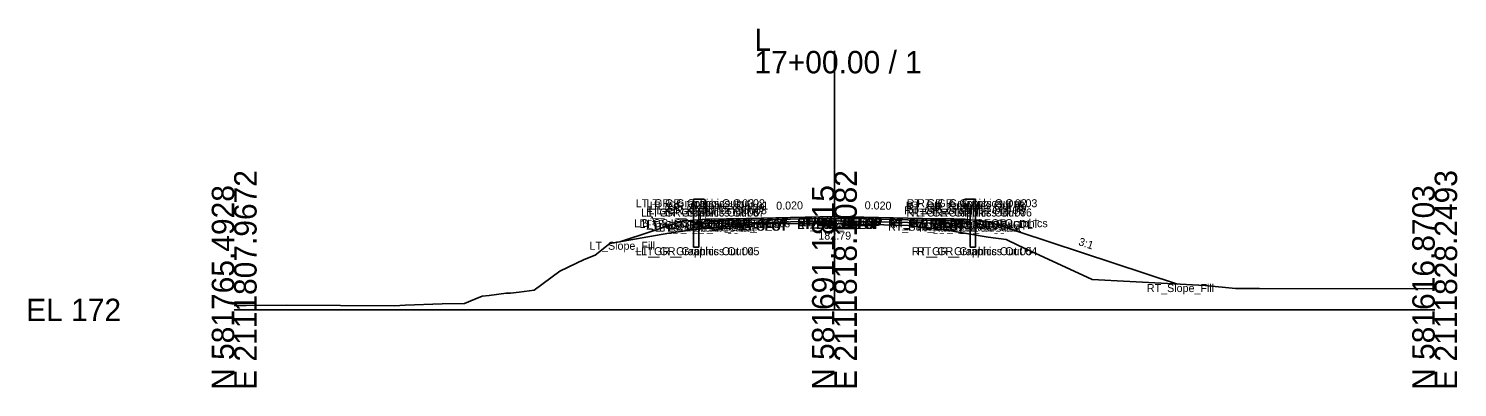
# Model space of a CAD drawing. Extents: x -26 to 3453, y -333 to 9539.
# Drawn here: x -25.7 to 152.8, y 7490.3 to 7535.2 of the extents above; entities that cross this region are included whole.
import ezdxf

# ---------------------------------------------------------------- set-up
doc = ezdxf.new("R2010")
doc.units = 0
for name, color, linetype in [('Default', 7, 'Continuous'), ('Exist Cross Section Cell', 7, 'Continuous'), ('Exist XS Center Line Elevation Label', 7, 'Continuous'), ('Exist XS Ground Line', 7, 'Continuous'), ('Prop CMT Guardrail Graphics', 7, 'Continuous'), ('Prop CMT Pvmt Course 1', 7, 'Continuous'), ('Prop CMT Pvmt Course 2', 7, 'Continuous'), ('Prop CMT Pvmt Course 3', 7, 'Continuous'), ('Prop CMT Pvmt Surface', 7, 'Continuous'), ('Prop CMT Pvmt Surface Shoulder', 7, 'Continuous'), ('Prop CMT Shld Paved Course 1', 7, 'Continuous'), ('Prop CMT Shld Paved Course 2', 7, 'Continuous'), ('Prop CMT Shld Paved Course 3', 7, 'Continuous'), ('Prop CMT Slope Grass', 7, 'Continuous'), ('Prop CMT Subgrade Earthwork', 7, 'Continuous'), ('Prop XS SE Text', 7, 'Continuous'), ('Prop XS Side Slope Text', 7, 'Continuous'), ('Scratch_Level_0', 7, 'Continuous')]:
    doc.layers.add(name, color=color, linetype=linetype)

msp = doc.modelspace()

# ---------------------------------------------------------------- linework, layer by layer
at = {"layer": 'Exist Cross Section Cell'}
for p, q in [((75, 7500), (75, 7532.38)), ((0, 7500), (75, 7500)), ((75, 7500), (150, 7500))]:
    msp.add_line(p, q, dxfattribs=at)
at = {"layer": 'Exist XS Ground Line'}
for p, q in [((46.92, 7508.3), (54.29, 7509.61)), ((54.29, 7509.61), (57.27, 7510.01)), ((57.27, 7510.01), (65.13, 7510.75)), ((65.13, 7510.75), (66.97, 7510.76)), ((66.97, 7510.76), (74.65, 7510.79)), ((74.65, 7510.79), (75, 7510.79)), ((75, 7510.79), (76.59, 7510.75)), ((76.59, 7510.75), (84.26, 7510.57)), ((84.26, 7510.57), (88.54, 7510.04)), ((88.54, 7510.04), (94.19, 7509.1)), ((94.19, 7509.1), (96.46, 7508.79)), ((45.09, 7506.86), (46.92, 7508.3)), ((96.46, 7508.79), (97.93, 7508.09)), ((97.93, 7508.09), (107.19, 7503.82)), ((40.68, 7504.84), (43.72, 7506.32)), ((43.72, 7506.32), (45.09, 7506.86)), ((37.47, 7502.46), (40.68, 7504.84)), ((107.19, 7503.82), (121.3, 7503.04)), ((31.86, 7501.81), (33.98, 7502.08)), ((33.98, 7502.08), (34.51, 7502.08)), ((34.51, 7502.08), (35.59, 7502.2)), ((35.59, 7502.2), (37.47, 7502.46)), ((121.3, 7503.04), (125.11, 7502.69)), ((125.11, 7502.69), (128.12, 7502.66)), ((128.12, 7502.66), (148.57, 7502.65)), ((148.57, 7502.65), (150, 7502.66)), ((0, 7500.55), (0.84, 7500.54)), ((0.84, 7500.54), (1.51, 7500.56)), ((1.51, 7500.56), (6.52, 7500.61)), ((6.52, 7500.61), (20.03, 7500.51)), ((20.03, 7500.51), (21.37, 7500.59)), ((21.37, 7500.59), (25.97, 7500.76)), ((25.97, 7500.76), (28.77, 7500.82)), ((28.77, 7500.82), (30.05, 7501.34)), ((30.05, 7501.34), (30.98, 7501.74)), ((30.98, 7501.74), (31.86, 7501.81))]:
    msp.add_line(p, q, dxfattribs=at)
at = {"layer": 'Prop CMT Guardrail Graphics'}
for points in [[(57.39, 7507.84), (57.39, 7513.84)], [(57.39, 7513.84), (58.72, 7513.84), (58.99, 7513.55)], [(58.99, 7512.97), (58.72, 7512.68), (58.05, 7512.68)], [(58.05, 7512.68), (58.05, 7507.84)], [(58.99, 7513.55), (58.72, 7513.26)], [(58.72, 7513.26), (58.99, 7512.97)], [(92.61, 7513.84), (91.28, 7513.84), (91.01, 7513.55)], [(91.01, 7513.55), (91.28, 7513.26)], [(91.28, 7513.26), (91.01, 7512.97)], [(91.01, 7512.97), (91.28, 7512.68), (91.95, 7512.68)], [(91.95, 7512.68), (91.95, 7507.84)], [(92.61, 7507.84), (92.61, 7513.84)], [(58.05, 7507.84), (57.39, 7507.84)], [(91.95, 7507.84), (92.61, 7507.84)]]:
    msp.add_lwpolyline(points, dxfattribs=at)
at = {"layer": 'Prop CMT Pvmt Course 1'}
for points in [[(75, 7511.66), (64, 7511.44)], [(64, 7511.24), (75, 7511.46)], [(64, 7511.44), (64, 7511.24)], [(75, 7511.46), (75, 7511.66)], [(75, 7511.66), (86, 7511.44)], [(75, 7511.46), (75, 7511.66)], [(86, 7511.24), (75, 7511.46)], [(86, 7511.44), (86, 7511.24)]]:
    msp.add_lwpolyline(points, dxfattribs=at)
msp.add_lwpolyline([(75, 7511.46), (75, 7511.54), (75, 7511.54), (75, 7511.46)], close=True, dxfattribs=at)
msp.add_lwpolyline([(75, 7511.46), (75, 7511.54), (75, 7511.54), (75, 7511.46)], close=True, dxfattribs=at)
at = {"layer": 'Prop CMT Pvmt Course 2'}
for points in [[(75, 7511.46), (64, 7511.24)], [(64, 7511.24), (64, 7510.9)], [(64, 7510.9), (75, 7511.12)], [(75, 7511.12), (75, 7511.46)], [(75, 7511.12), (75, 7511.46)], [(75, 7511.46), (86, 7511.24)], [(86, 7510.9), (75, 7511.12)], [(86, 7511.24), (86, 7510.9)]]:
    msp.add_lwpolyline(points, dxfattribs=at)
at = {"layer": 'Prop CMT Pvmt Course 3'}
for points in [[(75, 7511.12), (64, 7510.9)], [(64, 7510.9), (75, 7511.12)], [(64, 7510.9), (64, 7510.9)], [(75, 7511.12), (75, 7511.12)], [(75, 7511.12), (86, 7510.9)], [(86, 7510.9), (75, 7511.12)], [(75, 7511.12), (75, 7511.12)], [(86, 7510.9), (86, 7510.9)]]:
    msp.add_lwpolyline(points, dxfattribs=at)
at = {"layer": 'Prop CMT Pvmt Surface'}
for points in [[(75, 7511.66), (64, 7511.44)], [(75, 7511.66), (86, 7511.44)]]:
    msp.add_lwpolyline(points, dxfattribs=at)
at = {"layer": 'Prop CMT Pvmt Surface Shoulder'}
for points in [[(64, 7511.44), (59, 7511.34)], [(86, 7511.44), (91, 7511.34)]]:
    msp.add_lwpolyline(points, dxfattribs=at)
at = {"layer": 'Prop CMT Shld Paved Course 1'}
for points in [[(64, 7511.44), (59, 7511.34), (58.79, 7511.13)], [(58.79, 7511.13), (64, 7511.24)], [(64, 7511.24), (64, 7511.44)], [(86, 7511.44), (91, 7511.34), (91.21, 7511.13)], [(86, 7511.24), (86, 7511.44)], [(91.21, 7511.13), (86, 7511.24)]]:
    msp.add_lwpolyline(points, dxfattribs=at)
at = {"layer": 'Prop CMT Shld Paved Course 2'}
for points in [[(64, 7511.24), (58.79, 7511.13), (58.45, 7510.79)], [(58.45, 7510.79), (64, 7510.9)], [(64, 7510.9), (64, 7511.24)], [(86, 7511.24), (91.21, 7511.13), (91.55, 7510.79)], [(86, 7510.9), (86, 7511.24)], [(91.55, 7510.79), (86, 7510.9)]]:
    msp.add_lwpolyline(points, dxfattribs=at)
at = {"layer": 'Prop CMT Shld Paved Course 3'}
for points in [[(64, 7510.9), (58.45, 7510.79)], [(58.45, 7510.79), (64, 7510.9)], [(64, 7510.9), (64, 7510.9)], [(86, 7510.9), (91.55, 7510.79)], [(91.55, 7510.79), (86, 7510.9)], [(86, 7510.9), (86, 7510.9)], [(58.45, 7510.79), (58.45, 7510.79), (58.45, 7510.79)], [(91.55, 7510.79), (91.55, 7510.79), (91.55, 7510.79)]]:
    msp.add_lwpolyline(points, dxfattribs=at)
at = {"layer": 'Prop CMT Slope Grass'}
for points in [[(56, 7511.1), (48.17, 7508.52)], [(58.99, 7511.34), (56, 7511.1)], [(59, 7511.34), (58.99, 7511.34)], [(91, 7511.34), (91.01, 7511.34)], [(91.01, 7511.34), (94, 7511.1)], [(94, 7511.1), (117.86, 7503.23)]]:
    msp.add_lwpolyline(points, dxfattribs=at)
at = {"layer": 'Prop CMT Subgrade Earthwork'}
for points in [[(58.45, 7510.79), (57.98, 7511.26)], [(64, 7510.9), (58.45, 7510.79)], [(75, 7511.12), (64, 7510.9)], [(75, 7511.12), (86, 7510.9)], [(86, 7510.9), (91.55, 7510.79)], [(91.55, 7510.79), (92.02, 7511.26)]]:
    msp.add_lwpolyline(points, dxfattribs=at)

# ---------------------------------------------------------------- texts
at = {"layer": 'Default'}
msp.add_text('-', height=0.0001, dxfattribs=at).set_placement((0, 7500))
at = {"layer": 'Exist Cross Section Cell'}
for s, p in [('L', (65, 7532.38)), ('17+00.00 / 1', (65, 7529.58)), ('EL 172', (-26, 7498.6))]:
    msp.add_text(s, height=2.8, dxfattribs=at).set_placement(p)
for s, p in [('E 2111807.9672', (2.8, 7490)), ('E 2111818.1082', (77.8, 7490)), ('E 2111828.2493', (152.8, 7490)), ('N 581765.4928', (0, 7490)), ('N 581691.1815', (75, 7490)), ('N 581616.8703', (150, 7490))]:
    msp.add_text(s, height=2.8, rotation=90, dxfattribs=at).set_placement(p)
at = {"layer": 'Exist XS Center Line Elevation Label'}
msp.add_text('182.79', height=1, dxfattribs=at).set_placement((72.99, 7508.79))
at = {"layer": 'Prop XS SE Text'}
for rotation, p in [(1.1458, (67.73, 7512.52)), (358.8542, (78.77, 7512.59))]:
    msp.add_text('0.020', height=1, rotation=rotation, dxfattribs=at).set_placement(p)
at = {"layer": 'Prop XS Side Slope Text'}
for rotation, p in [(18.2629, (51.1, 7510.27)), (341.7371, (105.41, 7508.13))]:
    msp.add_text('3:1', height=1, rotation=rotation, dxfattribs=at).set_placement(p)
at = {"layer": 'Scratch_Level_0'}
for s, p in [('LT_GR_Graphics Out 03', (50.17, 7512.84)), ('LT_GR_Graphics Out 06', (50.83, 7511.68)), ('LT_GR_Graphics Out 07', (51.48, 7511.68)), ('LT_GR_Graphics Out 09', (51.49, 7512.26)), ('LT_GR_Graphics Out 02', (51.52, 7512.84)), ('LT_GR_Graphics Out 08', (51.76, 7511.97)), ('LT_GR_Graphics Out 01', (51.94, 7512.55)), ('RT_GR_Graphics Out 08', (83.72, 7511.97)), ('RT_GR_Graphics Out 01', (83.9, 7512.55)), ('RT_GR_Graphics Out 07', (83.98, 7511.68)), ('RT_GR_Graphics Out 09', (84, 7512.26)), ('RT_GR_Graphics Out 02', (84.02, 7512.84)), ('RT_GR_Graphics Out 06', (84.66, 7511.68)), ('RT_GR_Graphics Out 03', (85.34, 7512.84)), ('LT_GS_OS_GR_Face_Graphics', (49.99, 7510.34)), ('LT_Sub_Trench_Out_DLT', (50.63, 7510.26)), ('LT_GS_OS_CTL', (51.46, 7510.1)), ('LT_PS2_OEOP', (54.57, 7510.13)), ('LT_PS1_OEOP', (54.91, 7510.34)), ('LT_PV2_OEOT', (59.75, 7510.24)), ('LT_PV3_OEOT', (59.75, 7509.9)), ('LT_Sub_OEOT', (59.77, 7509.9)), ('LT_PV1_OEOT', (59.87, 7510.44)), ('RT_PV2_OEEOP', (70.33, 7510.46)), ('RT_PV3_OEEOP', (70.33, 7510.12)), ('RT_Sub_OEEOP', (70.36, 7510.12)), ('LT_PV2_OEEOP', (70.39, 7510.46)), ('LT_PV3_OEEOP', (70.39, 7510.12)), ('LT_Sub_OEEOP', (70.42, 7510.12)), ('RT_PV1_OEEOP', (70.45, 7510.54)), ('LT_PV1_OEEOP', (70.51, 7510.54)), ('RT_PV2_IEEOP', (70.71, 7510.46)), ('LT_PV2_IEEOP', (70.77, 7510.46)), ('RT_PV1_IEEOP', (70.83, 7510.54)), ('LT_PV1_IEEOP', (70.89, 7510.54)), ('PV2_PGL', (72.35, 7510.46)), ('PV1_PGL', (72.47, 7510.66)), ('RT_PV2_OEOT', (81.69, 7510.24)), ('RT_PV3_OEOT', (81.69, 7509.9)), ('RT_Sub_OEOT', (81.71, 7509.9)), ('RT_PV1_OEOT', (81.81, 7510.44)), ('RT_GS_OS_GR_Face_Graphics', (81.95, 7510.34)), ('RT_Sub_Trench_Out_DLT', (84.61, 7510.26)), ('RT_PS1_OEOP', (86.85, 7510.34)), ('RT_PS2_OEOP', (86.94, 7510.13)), ('RT_GS_OS_CTL', (89.4, 7510.1)), ('LT_Sub_Trench_Out', (52.56, 7509.79)), ('LT_PS3_Shelf_Out', (53.1, 7509.79)), ('LT_PS3_OEOP', (54.23, 7509.79)), ('RT_Sub_Trench_Out', (85.6, 7509.79)), ('RT_PS3_Shelf_Out', (86.15, 7509.79)), ('RT_PS3_OEOP', (87.28, 7509.79)), ('LT_Slope_Fill', (44.4, 7507.52)), ('LT_GR_Graphics Out 04', (50.16, 7506.84)), ('LT_GR_Graphics Out 05', (50.83, 7506.84)), ('RT_GR_Graphics Out 05', (84.67, 7506.84)), ('RT_GR_Graphics Out 04', (85.32, 7506.84)), ('RT_Slope_Fill', (114.04, 7502.23))]:
    msp.add_text(s, height=1, dxfattribs=at).set_placement(p)

doc.saveas('drawing.dxf')
